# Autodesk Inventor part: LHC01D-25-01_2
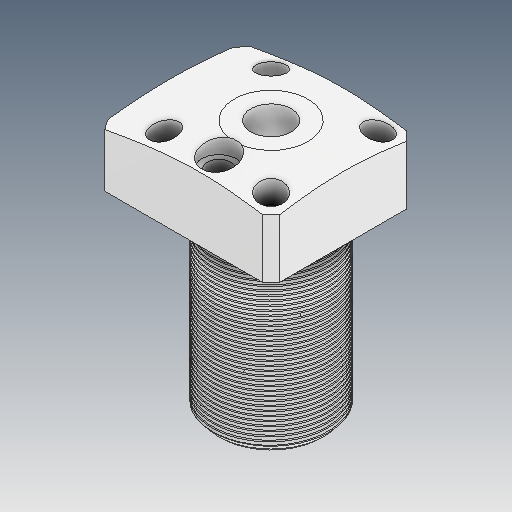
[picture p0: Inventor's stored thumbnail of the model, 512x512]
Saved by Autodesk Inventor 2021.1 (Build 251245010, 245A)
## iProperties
Created: 2021-06
Part Number: LHC01D-25-01_2
Material: Ogólny
Document SubType Name: Modeling
Designer: user
Density: 1 g/cm^3
Appearance: Domyślna
Author: user
Revision Number: ÈÎºÎ
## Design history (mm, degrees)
feature "NONE"
node "Bryła1"
